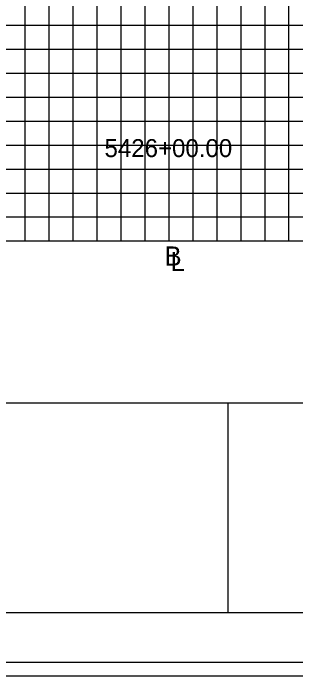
# Model space of a CAD drawing. Extents: x 967 to 1326, y 964 to 3144.
# Drawn here: x 1147 to 1170.6, y 1523.7 to 1579 of the extents above; entities that cross this region are included whole.
import ezdxf

# ---------------------------------------------------------------- set-up
doc = ezdxf.new("R2010")
doc.units = 0
for name, color, linetype in [('Default', 7, 'Continuous'), ('RD_GPK_XS_Cell', 7, 'Continuous'), ('RD_XS_ExGround', 7, 'Continuous'), ('RD_XS_ExPaveRet', 7, 'Continuous'), ('RD_XS_Misc_Line', 7, 'Continuous'), ('RD_XS_TX_Elev_EX', 7, 'Continuous'), ('RD_XS_TX_Station', 7, 'Continuous')]:
    doc.layers.add(name, color=color, linetype=linetype)

msp = doc.modelspace()

# ---------------------------------------------------------------- linework, layer by layer
at = {"layer": 'RD_GPK_XS_Cell'}
for p, q in [((1150, 1560), (1150, 1730)), ((1160, 1560), (1160, 1730)), ((1170, 1560), (1170, 1730)), ((1000, 1570), (1320, 1570)), ((1000, 1560), (1320, 1560))]:
    msp.add_line(p, q, dxfattribs=at)
at = {"layer": 'RD_XS_ExGround'}
for p, q in [((1148, 1560), (1148, 1730)), ((1152, 1560), (1152, 1730)), ((1154, 1560), (1154, 1730)), ((1156, 1560), (1156, 1730)), ((1158, 1560), (1158, 1730)), ((1162, 1560), (1162, 1730)), ((1164, 1560), (1164, 1730)), ((1166, 1560), (1166, 1730)), ((1168, 1560), (1168, 1730)), ((1000, 1578), (1320, 1578)), ((1000, 1576), (1320, 1576)), ((1000, 1574), (1320, 1574)), ((1000, 1572), (1320, 1572)), ((1000, 1568), (1320, 1568)), ((1000, 1566), (1320, 1566)), ((1000, 1564), (1320, 1564)), ((1000, 1562), (1320, 1562))]:
    msp.add_line(p, q, dxfattribs=at)
at = {"layer": 'RD_XS_ExPaveRet'}
for points in [[(967.409, 1523.72), (1326.285, 1523.72), (1326.285, 1743.72), (967.409, 1743.72)], [(988.525, 1524.84), (1326.285, 1524.84), (1326.285, 1742.6), (988.525, 1742.6)]]:
    msp.add_lwpolyline(points, close=True, dxfattribs=at)
at = {"layer": 'RD_XS_TX_Elev_EX'}
for p, q in [((996.114, 1546.486), (1323.886, 1546.486)), ((1164.932, 1528.983), (1164.932, 1546.526)), ((1323.886, 1528.983), (996.114, 1528.983))]:
    msp.add_line(p, q, dxfattribs=at)
at = {"layer": 'RD_XS_TX_Station'}
msp.add_lwpolyline([(967.409, 1523.72), (1326.285, 1523.72), (1326.285, 1743.72), (967.409, 1743.72)], close=True, dxfattribs=at)

# ---------------------------------------------------------------- texts
at = {"layer": 'Default'}
msp.add_text('5426+00.00', height=1.5, dxfattribs=at).set_placement((1154.611, 1566.997))
at = {"layer": 'RD_XS_Misc_Line'}
for s, p in [('B', (1159.615, 1557.941)), ('L', (1160.124, 1557.491))]:
    msp.add_text(s, height=1.6, dxfattribs=at).set_placement(p)

doc.saveas('drawing.dxf')
